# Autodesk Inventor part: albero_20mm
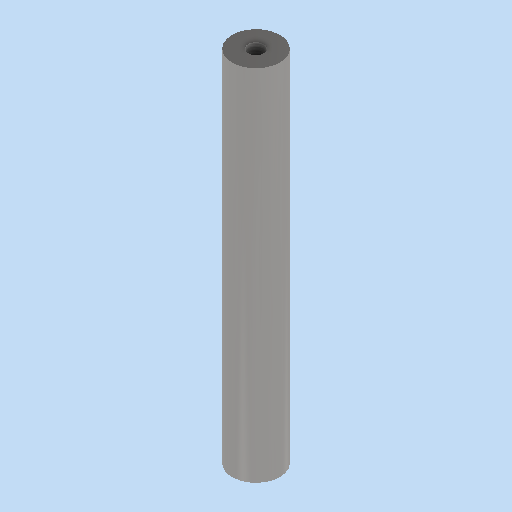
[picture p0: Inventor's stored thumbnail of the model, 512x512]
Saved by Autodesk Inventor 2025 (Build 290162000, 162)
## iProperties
Created: 2025-04
Part Number: albero_20mm
Material: Alluminio 6061
Document SubType Name: Modeling
Designer: R5800u
Density: 2.7 g/cm^3
Appearance: Acciaio - Lucido
Author: R5800u
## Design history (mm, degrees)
sketch "Schizzo1"
  geometry: C1 r 10 at (0, 0); 1 further point
  constraints: 1 centre point, 1 coincident
  dimensions: "d0" = 20 diameter of C1
extrude "Estrusione1" new body sketch "Schizzo1" distance "d1" = 150; taper "d2" = 0 deg
sketch "Schizzo2"
  geometry: C1 r 10 at (0, 0) reference; 2 further points
  constraints: 1 coincident
hole "Foro1" sketch "Schizzo2" at (0, 0) diameter "d3" = 6.647; stored, may be unused: countersink angle "d7" = 90 deg, drill point angle "d9" = 118 deg; dims "d4" = 20, "d5" = 15, "d6" = 4, "d8" = 22.2
node "Solido1"
